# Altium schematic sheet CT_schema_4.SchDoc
size 301 x 279 mm
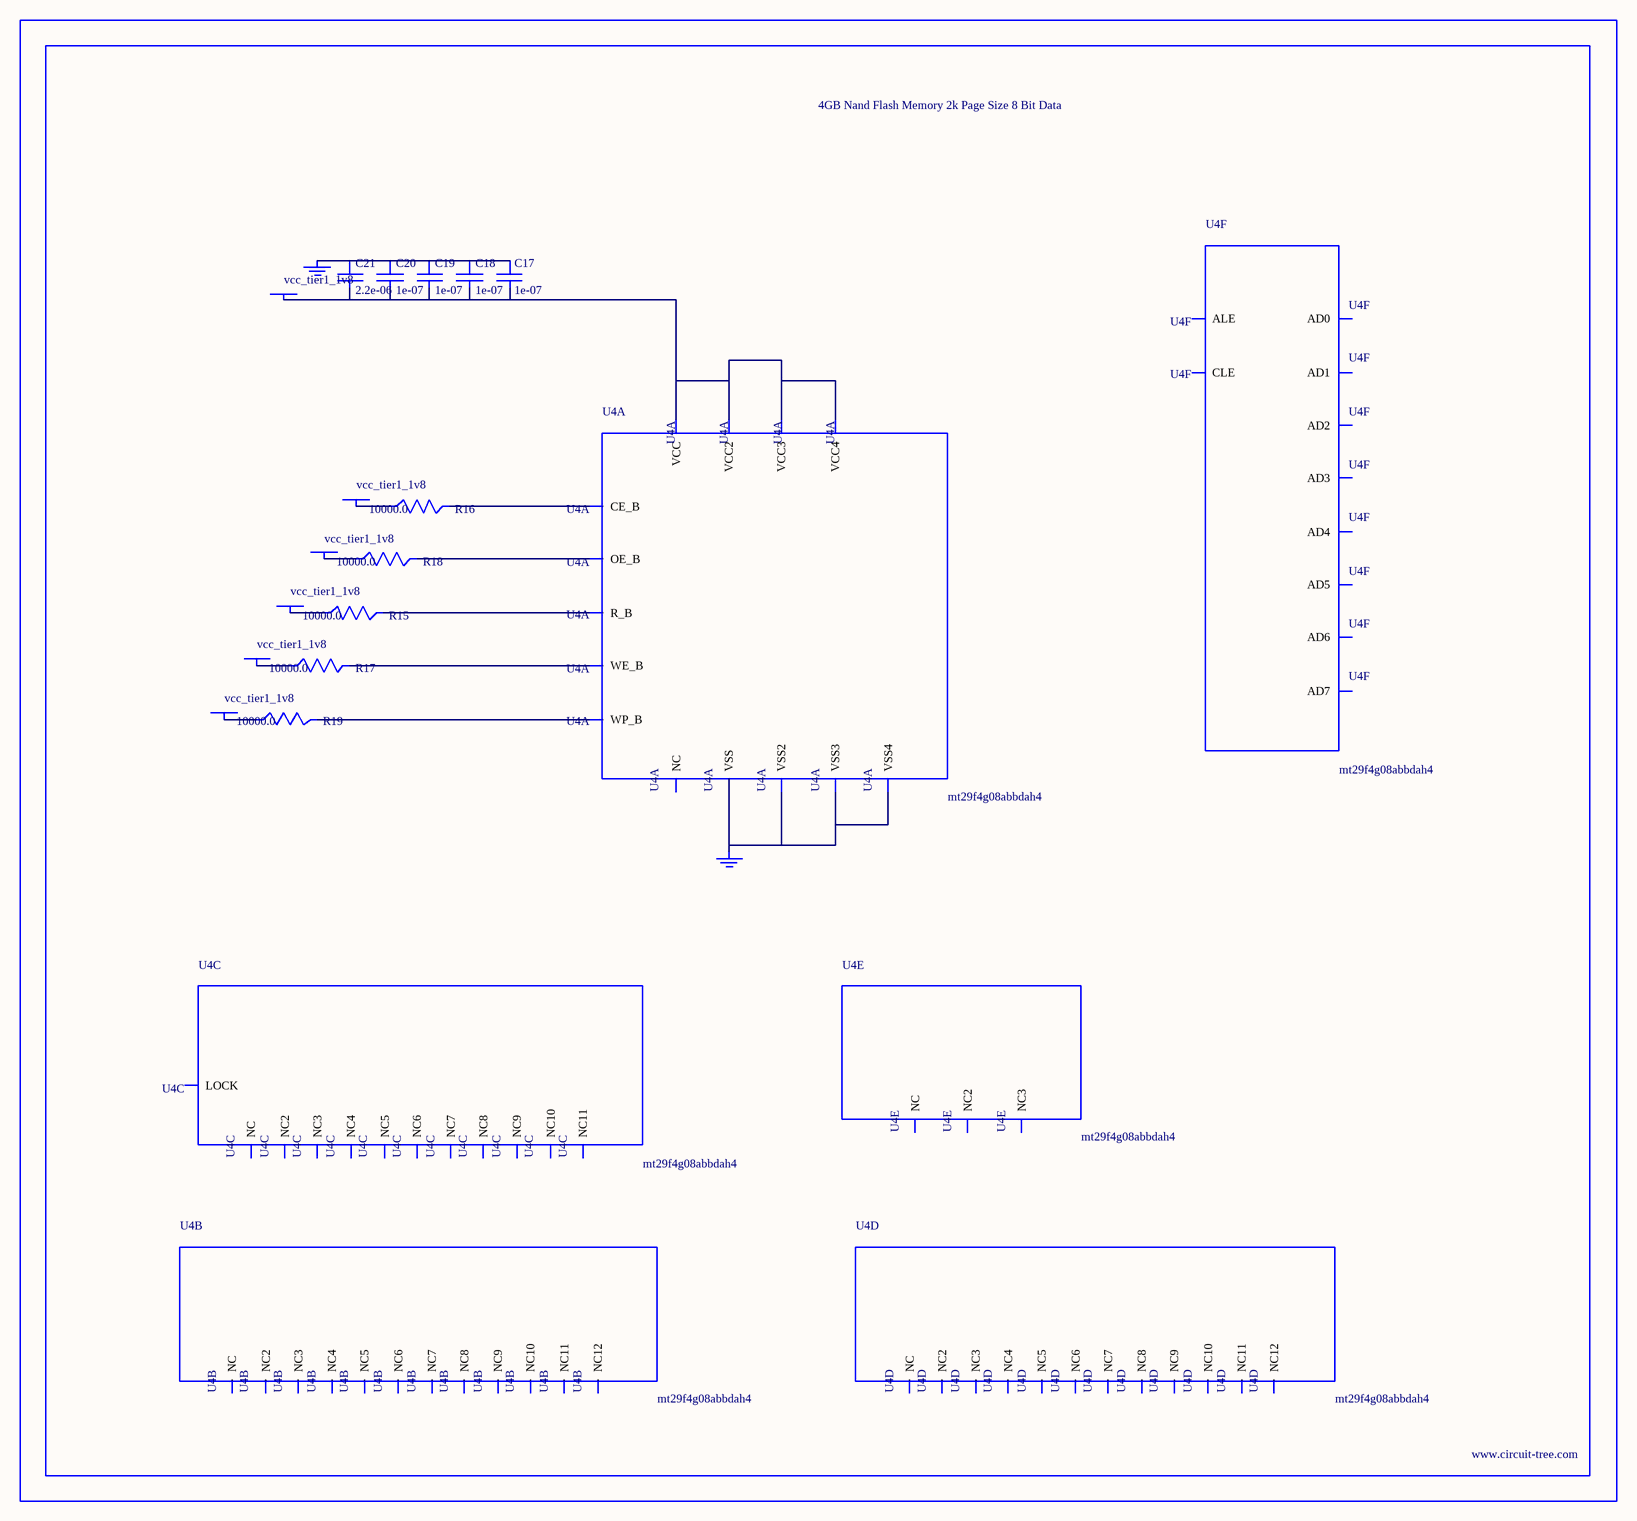
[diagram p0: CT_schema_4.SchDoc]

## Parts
BORDER3  (no value)
C17  1e-07  [C0402]
C18  1e-07  [C0402]
C19  1e-07  [C0402]
C20  1e-07  [C0402]
C21  2.2e-06  [C0603]
GND_INSTANCE_3_0  (no value)
GND_INSTANCE_3_1  (no value)
POWER_INSTANCE_3_0  vcc_tier1_1v8
POWER_INSTANCE_3_1  vcc_tier1_1v8
POWER_INSTANCE_3_2  vcc_tier1_1v8
POWER_INSTANCE_3_3  vcc_tier1_1v8
POWER_INSTANCE_3_4  vcc_tier1_1v8
POWER_INSTANCE_3_5  vcc_tier1_1v8
R15  10000.0  [R0603]
R16  10000.0  [R0603]
R17  10000.0  [R0603]
R18  10000.0  [R0603]
R19  10000.0  [R0603]
U4  mt29f4g08abbdah4  [VFBGA-63]  (parts A,B,C,D,E,F of 6)

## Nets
NetC17_1: C17.1 C18.1 C19.1 C20.1 C21.1 GND_INSTANCE_3_0.0(GND)
NetC17_2: C17.2 C18.2 C19.2 C20.2 C21.2 POWER_INSTANCE_3_0.0(PWR) U4.D3(VCC) U4.G4(VCC2) U4.H8(VCC3) U4.J6(VCC4)
NetGND_INSTANCE_3_1_0: GND_INSTANCE_3_1.0(GND) U4.C5(VSS) U4.F7(VSS2) U4.K3(VSS3) U4.K8(VSS4)
NetPOWER_INSTANCE_3_1_0: POWER_INSTANCE_3_1.0(PWR) R15.1
NetPOWER_INSTANCE_3_2_0: POWER_INSTANCE_3_2.0(PWR) R16.1
NetPOWER_INSTANCE_3_3_0: POWER_INSTANCE_3_3.0(PWR) R17.1
NetPOWER_INSTANCE_3_4_0: POWER_INSTANCE_3_4.0(PWR) R18.1
NetPOWER_INSTANCE_3_5_0: POWER_INSTANCE_3_5.0(PWR) R19.1
NetR15_2: R15.2 U4.C8(R_B)
NetR16_2: R16.2 U4.C6(CE_B)
NetR17_2: R17.2 U4.C7(WE_B)
NetR18_2: R18.2 U4.D4(OE_B)
NetR19_2: R19.2 U4.C3(WP_B)

Not connected (* = marked no-connect by the designer): U4 A1(NC) A2(NC3) A9(NC4) A10(NC2) B1(NC5) B9(NC7) B10(NC6) C4(ALE) D5(CLE) D6(NC8) D7(NC9) D8(NC10) E3(NC11) E4(NC12) E5(NC) E6(NC2) E7(NC3) E8(NC4) F3(NC5) F4(NC6) F5(NC7) F6(NC8) F8(NC9) G3(NC) G5(LOCK) G6(NC10) G7(NC11) G8(NC) H3(NC2) H4(AD0) H5(NC3) H6(NC4) H7(NC5) J3(NC6) J4(AD1) J5(NC7) J7(AD5) J8(AD7) K4(AD2) K5(AD3) K6(AD4) K7(AD6) L1(NC8) L2(NC10) L9(NC11) L10(NC9) M1(NC12) M2(NC2) M9(NC3) M10(NC)

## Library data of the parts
BORDER3 = BORDER_PAGE3
C17-C20 = C0402C104K3RACTU
C21 = C0603C225K8RACTU
GND_INSTANCE_3_0 GND_INSTANCE_3_1 = GND
POWER_INSTANCE_3_0-POWER_INSTANCE_3_5 = PWR
R15-R19 = RC0603JR-0710KL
